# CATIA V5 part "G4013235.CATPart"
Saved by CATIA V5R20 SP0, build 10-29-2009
Part number: G4013235
Revision: 4
Definition: design
Nomenclature: G4013235
Source: made
Description: NOT SPECIFIED
Bounding box of the stored display mesh (mm): x 0 to 35, y -22.5 to 22.5, z -22.5 to 22.5
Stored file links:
  C:\Users\Raffaele\Desktop\3D X SITO CF\BOLEX\25-BUSH REF 401\G4013235.CATPart
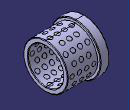
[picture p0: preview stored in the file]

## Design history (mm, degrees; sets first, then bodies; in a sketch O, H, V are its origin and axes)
Body1 "MANIFOLD_SOLID_BREP #8155" (main body)
  Solid1: solid without history
Body2 "MANIFOLD_SOLID_BREP #8302"
  Solid2: solid without history
Body3 "MANIFOLD_SOLID_BREP #8449"
  Solid3: solid without history
Body4 "MANIFOLD_SOLID_BREP #8596"
  Solid4: solid without history
Body5 "MANIFOLD_SOLID_BREP #8743"
  Solid5: solid without history
Body6 "MANIFOLD_SOLID_BREP #8892"
  Solid6: solid without history
Body7 "MANIFOLD_SOLID_BREP #9041"
  Solid7: solid without history
Body8 "MANIFOLD_SOLID_BREP #9190"
  Solid8: solid without history
Body9 "MANIFOLD_SOLID_BREP #9339"
  Solid9: solid without history
Body10 "MANIFOLD_SOLID_BREP #9488"
  Solid10: solid without history
Body11 "MANIFOLD_SOLID_BREP #9637"
  Solid11: solid without history
Body12 "MANIFOLD_SOLID_BREP #9786"
  Solid12: solid without history
Body13 "MANIFOLD_SOLID_BREP #9935"
  Solid13: solid without history
Body14 "MANIFOLD_SOLID_BREP #10084"
  Solid14: solid without history
Body15 "MANIFOLD_SOLID_BREP #10233"
  Solid15: solid without history
Body16 "MANIFOLD_SOLID_BREP #10382"
  Solid16: solid without history
Body17 "MANIFOLD_SOLID_BREP #10531"
  Solid17: solid without history
Body18 "MANIFOLD_SOLID_BREP #10680"
  Solid18: solid without history
Body19 "MANIFOLD_SOLID_BREP #10829"
  Solid19: solid without history
Body20 "MANIFOLD_SOLID_BREP #10978"
  Solid20: solid without history
Body21 "MANIFOLD_SOLID_BREP #11127"
  Solid21: solid without history
Body22 "MANIFOLD_SOLID_BREP #11276"
  Solid22: solid without history
Body23 "MANIFOLD_SOLID_BREP #11425"
  Solid23: solid without history
Body24 "MANIFOLD_SOLID_BREP #11574"
  Solid24: solid without history
Body25 "MANIFOLD_SOLID_BREP #11723"
  Solid25: solid without history
Body26 "MANIFOLD_SOLID_BREP #11872"
  Solid26: solid without history
Body27 "MANIFOLD_SOLID_BREP #12021"
  Solid27: solid without history
Body28 "MANIFOLD_SOLID_BREP #12170"
  Solid28: solid without history
Body29 "MANIFOLD_SOLID_BREP #12319"
  Solid29: solid without history
Body30 "MANIFOLD_SOLID_BREP #12468"
  Solid30: solid without history
Body31 "MANIFOLD_SOLID_BREP #12617"
  Solid31: solid without history
Body32 "MANIFOLD_SOLID_BREP #12764"
  Solid32: solid without history
Body33 "MANIFOLD_SOLID_BREP #12911"
  Solid33: solid without history
Body34 "MANIFOLD_SOLID_BREP #13060"
  Solid34: solid without history
Body35 "MANIFOLD_SOLID_BREP #13209"
  Solid35: solid without history
Body36 "MANIFOLD_SOLID_BREP #13358"
  Solid36: solid without history
Body37 "MANIFOLD_SOLID_BREP #13507"
  Solid37: solid without history
Body38 "MANIFOLD_SOLID_BREP #13656"
  Solid38: solid without history
Body39 "MANIFOLD_SOLID_BREP #13805"
  Solid39: solid without history
Body40 "MANIFOLD_SOLID_BREP #13954"
  Solid40: solid without history
Body41 "MANIFOLD_SOLID_BREP #14103"
  Solid41: solid without history
Body42 "MANIFOLD_SOLID_BREP #14252"
  Solid42: solid without history
Body43 "MANIFOLD_SOLID_BREP #14401"
  Solid43: solid without history
Body44 "MANIFOLD_SOLID_BREP #14550"
  Solid44: solid without history
Body45 "MANIFOLD_SOLID_BREP #14699"
  Solid45: solid without history
Body46 "MANIFOLD_SOLID_BREP #14848"
  Solid46: solid without history
Body47 "MANIFOLD_SOLID_BREP #14997"
  Solid47: solid without history
Body48 "MANIFOLD_SOLID_BREP #15144"
  Solid48: solid without history
Body49 "MANIFOLD_SOLID_BREP #15291"
  Solid49: solid without history
Body50 "MANIFOLD_SOLID_BREP #15440"
  Solid50: solid without history
Body51 "MANIFOLD_SOLID_BREP #15589"
  Solid51: solid without history
Body52 "MANIFOLD_SOLID_BREP #15738"
  Solid52: solid without history
Body53 "MANIFOLD_SOLID_BREP #15887"
  Solid53: solid without history
Body54 "MANIFOLD_SOLID_BREP #16036"
  Solid54: solid without history
Body55 "MANIFOLD_SOLID_BREP #16185"
  Solid55: solid without history
Body56 "MANIFOLD_SOLID_BREP #16334"
  Solid56: solid without history
Body57 "MANIFOLD_SOLID_BREP #16483"
  Solid57: solid without history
